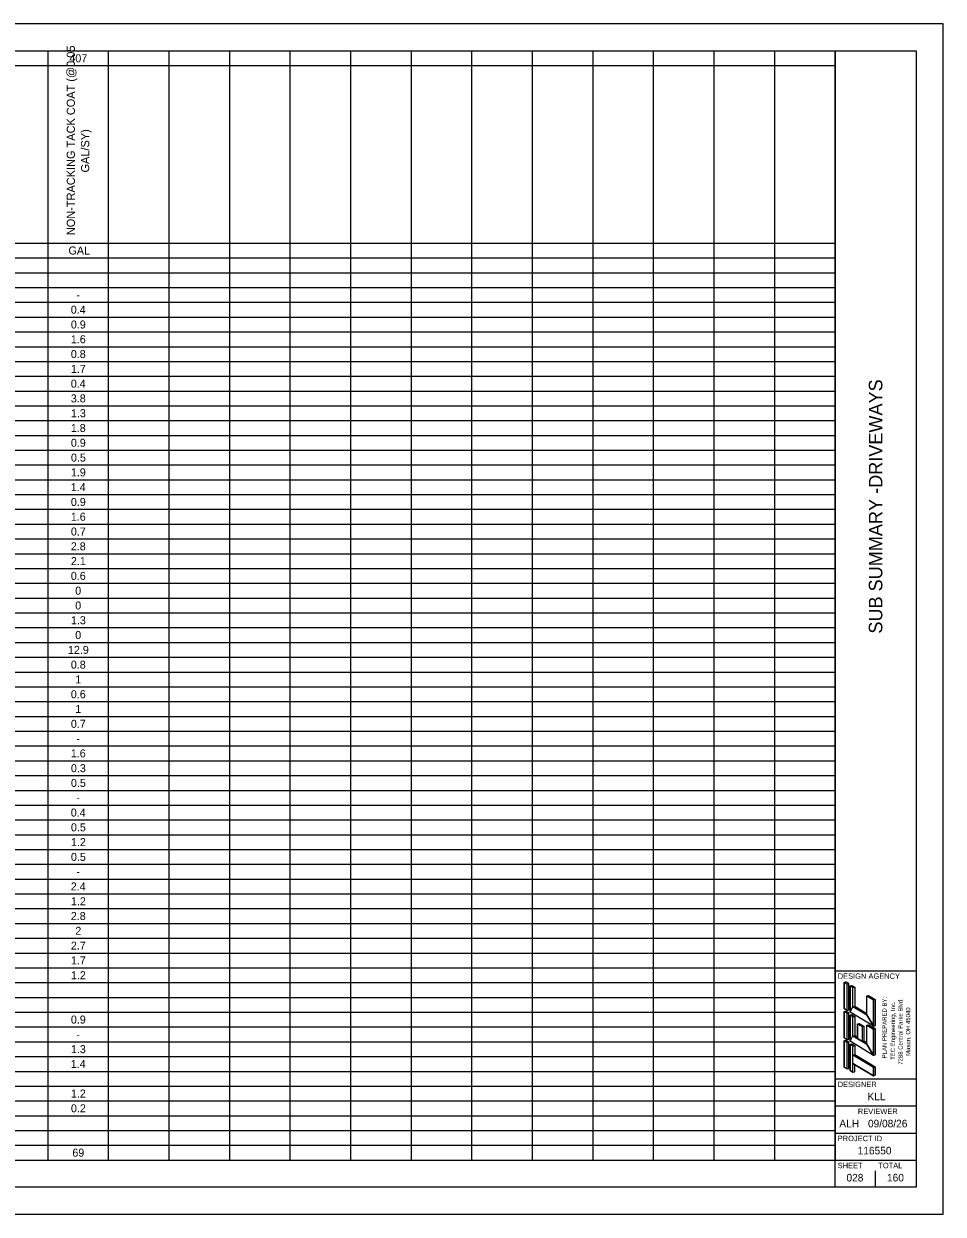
# Model space of a CAD drawing. Extents: x 0 to 34, y 0 to 22.
# Drawn here: x 17 to 34, y 0 to 22 of the extents above; entities that cross this region are included whole.
import ezdxf

# ---------------------------------------------------------------- set-up
doc = ezdxf.new("R2010")
doc.units = 0
for name, color, linetype in [('Default', 7, 'Continuous'), ('SH_Border', 7, 'Continuous'), ('SH_Cut_Line', 7, 'Continuous'), ('SH_Data', 7, 'Continuous'), ('SH_Text', 7, 'Continuous')]:
    doc.layers.add(name, color=color, linetype=linetype)

msp = doc.modelspace()

# ---------------------------------------------------------------- linework, layer by layer
at = {"layer": 'SH_Border'}
for p, q in [((32, 0.5), (32, 21.5)), ((32, 4.5), (33.5, 4.5)), ((32, 2.5), (33.5, 2.5)), ((32, 2), (33.5, 2)), ((32, 1.5), (33.5, 1.5)), ((32, 1), (33.5, 1))]:
    msp.add_line(p, q, dxfattribs=at)
msp.add_lwpolyline([(1.5, 21.5), (33.5, 21.5), (33.5, 0.5), (1.5, 0.5)], close=True, dxfattribs=at)
at = {"layer": 'SH_Cut_Line'}
msp.add_lwpolyline([(0, 0), (34, 0), (34, 22), (0, 22)], close=True, dxfattribs=at)
at = {"layer": 'SH_Data'}
for p, q in [((32.75, 3.5), (32.75, 3.5)), ((32.375, 0.675), (32.375, 0.675)), ((32.75, 0.5), (32.75, 0.8))]:
    msp.add_line(p, q, dxfattribs=at)
at = {"layer": 'SH_Text'}
for p, q in [((1.5, 21.5), (32, 21.5)), ((17.442, 21.5), (17.442, 1)), ((18.562, 21.5), (18.562, 1)), ((19.681, 21.5), (19.681, 1)), ((20.801, 21.5), (20.801, 1)), ((21.921, 21.5), (21.921, 1)), ((23.041, 21.5), (23.041, 1)), ((24.161, 21.5), (24.161, 1)), ((25.281, 21.5), (25.281, 1)), ((26.401, 21.5), (26.401, 1)), ((27.521, 21.5), (27.521, 1)), ((28.64, 21.5), (28.64, 1)), ((29.76, 21.5), (29.76, 1)), ((30.88, 21.5), (30.88, 1)), ((32, 21.5), (32, 1)), ((8.483, 21.227), (32, 21.227)), ((8.483, 17.947), (32, 17.947)), ((1.5, 17.673), (32, 17.673)), ((1.5, 17.4), (32, 17.4)), ((1.5, 17.127), (32, 17.127)), ((1.5, 16.853), (32, 16.853)), ((1.5, 16.58), (32, 16.58)), ((1.5, 16.307), (32, 16.307)), ((1.5, 16.033), (32, 16.033)), ((1.5, 15.76), (32, 15.76)), ((1.5, 15.487), (32, 15.487)), ((1.5, 15.213), (32, 15.213)), ((1.5, 14.94), (32, 14.94)), ((1.5, 14.667), (32, 14.667)), ((1.5, 14.393), (32, 14.393)), ((1.5, 14.12), (32, 14.12)), ((1.5, 13.847), (32, 13.847)), ((1.5, 13.573), (32, 13.573)), ((1.5, 13.3), (32, 13.3)), ((1.5, 13.027), (32, 13.027)), ((1.5, 12.753), (32, 12.753)), ((1.5, 12.48), (32, 12.48)), ((1.5, 12.207), (32, 12.207)), ((1.5, 11.933), (32, 11.933)), ((1.5, 11.66), (32, 11.66)), ((1.5, 11.387), (32, 11.387)), ((1.5, 11.113), (32, 11.113)), ((1.5, 10.84), (32, 10.84)), ((1.5, 10.567), (32, 10.567)), ((1.5, 10.293), (32, 10.293)), ((1.5, 10.02), (32, 10.02)), ((1.5, 9.747), (32, 9.747)), ((1.5, 9.473), (32, 9.473)), ((1.5, 9.2), (32, 9.2)), ((1.5, 8.927), (32, 8.927)), ((1.5, 8.653), (32, 8.653)), ((1.5, 8.38), (32, 8.38)), ((1.5, 8.107), (32, 8.107)), ((1.5, 7.833), (32, 7.833)), ((1.5, 7.56), (32, 7.56)), ((1.5, 7.287), (32, 7.287)), ((1.5, 7.013), (32, 7.013)), ((1.5, 6.74), (32, 6.74)), ((1.5, 6.467), (32, 6.467)), ((1.5, 6.193), (32, 6.193)), ((1.5, 5.92), (32, 5.92)), ((1.5, 5.647), (32, 5.647)), ((1.5, 5.373), (32, 5.373)), ((1.5, 5.1), (32, 5.1)), ((1.5, 4.827), (32, 4.827)), ((1.5, 4.553), (32, 4.553)), ((1.5, 4.28), (32, 4.28)), ((32.169, 4.285), (32.201, 4.294)), ((32.169, 3.799), (32.169, 4.285)), ((32.223, 4.253), (32.169, 4.285)), ((32.255, 4.261), (32.201, 4.294)), ((32.223, 4.253), (32.255, 4.261)), ((32.223, 3.767), (32.223, 4.253)), ((32.255, 3.775), (32.255, 4.261)), ((32.277, 4.221), (32.309, 4.229)), ((32.331, 4.188), (32.277, 4.221)), ((32.277, 3.735), (32.277, 4.221)), ((32.309, 4.229), (32.363, 4.196)), ((32.331, 4.188), (32.363, 4.196)), ((32.331, 3.837), (32.331, 4.188)), ((32.363, 4.196), (32.363, 3.845)), ((1.5, 4.007), (32, 4.007)), ((32.587, 4.034), (32.62, 4.042)), ((32.587, 3.683), (32.587, 4.034)), ((32.709, 3.961), (32.587, 4.034)), ((32.62, 4.042), (32.741, 3.97)), ((32.709, 3.961), (32.741, 3.97)), ((32.709, 3.475), (32.709, 3.961)), ((32.741, 3.97), (32.741, 3.484)), ((32.223, 3.767), (32.169, 3.799)), ((32.169, 3.745), (32.201, 3.754)), ((32.169, 3.259), (32.169, 3.745)), ((32.223, 3.713), (32.169, 3.745)), ((32.255, 3.722), (32.201, 3.754)), ((32.223, 3.767), (32.255, 3.775)), ((32.331, 3.837), (32.363, 3.845)), ((32.587, 3.683), (32.331, 3.837)), ((32.363, 3.845), (32.587, 3.711)), ((1.5, 3.733), (32, 3.733)), ((32.223, 3.713), (32.255, 3.722)), ((32.223, 3.227), (32.223, 3.713)), ((32.255, 3.236), (32.255, 3.722)), ((32.709, 3.475), (32.277, 3.735)), ((32.277, 3.681), (32.309, 3.689)), ((32.277, 3.195), (32.277, 3.681)), ((32.331, 3.648), (32.277, 3.681)), ((32.309, 3.689), (32.363, 3.656)), ((32.331, 3.648), (32.363, 3.656)), ((32.331, 3.297), (32.331, 3.648)), ((32.363, 3.656), (32.363, 3.305)), ((32.415, 3.519), (32.448, 3.527)), ((32.448, 3.527), (32.535, 3.474)), ((1.5, 3.46), (32, 3.46)), ((32.331, 3.297), (32.363, 3.305)), ((32.363, 3.305), (32.415, 3.274)), ((32.415, 3.519), (32.415, 3.247)), ((32.415, 3.519), (32.503, 3.466)), ((32.503, 3.466), (32.535, 3.474)), ((32.503, 3.466), (32.503, 3.194)), ((32.535, 3.474), (32.535, 3.202)), ((32.587, 3.494), (32.62, 3.502)), ((32.587, 3.143), (32.587, 3.494)), ((32.709, 3.421), (32.587, 3.494)), ((32.62, 3.502), (32.741, 3.43)), ((32.709, 3.475), (32.741, 3.484)), ((32.709, 3.421), (32.741, 3.43)), ((32.709, 2.935), (32.709, 3.421)), ((32.741, 3.43), (32.741, 2.944)), ((1.5, 3.187), (32, 3.187)), ((32.223, 3.227), (32.169, 3.259)), ((32.169, 3.205), (32.201, 3.215)), ((32.169, 2.719), (32.169, 3.205)), ((32.223, 3.173), (32.169, 3.205)), ((32.255, 3.181), (32.201, 3.215)), ((32.222, 3.173), (32.255, 3.181)), ((32.223, 3.227), (32.255, 3.236)), ((32.223, 2.687), (32.223, 3.173)), ((32.255, 2.695), (32.255, 3.181)), ((32.709, 2.935), (32.277, 3.195)), ((32.277, 3.141), (32.309, 3.151)), ((32.331, 3.108), (32.277, 3.141)), ((32.277, 2.655), (32.277, 3.141)), ((32.309, 3.151), (32.363, 3.116)), ((32.415, 3.247), (32.331, 3.297)), ((32.331, 3.108), (32.363, 3.116)), ((32.331, 2.944), (32.331, 3.108)), ((32.363, 3.116), (32.363, 2.952)), ((32.503, 3.194), (32.535, 3.202)), ((32.587, 3.143), (32.503, 3.194)), ((32.535, 3.202), (32.587, 3.171)), ((1.5, 2.913), (32, 2.913)), ((32.331, 2.944), (32.363, 2.952)), ((32.331, 2.944), (32.709, 2.717)), ((32.363, 2.952), (32.741, 2.725)), ((32.709, 2.935), (32.741, 2.944)), ((1.5, 2.64), (32, 2.64)), ((32.223, 2.687), (32.169, 2.719)), ((32.223, 2.687), (32.255, 2.695)), ((32.331, 2.622), (32.277, 2.655)), ((32.331, 2.787), (32.709, 2.56)), ((32.331, 2.622), (32.331, 2.787)), ((32.363, 2.63), (32.363, 2.767)), ((32.709, 2.717), (32.741, 2.725)), ((32.709, 2.56), (32.709, 2.717)), ((32.741, 2.725), (32.741, 2.568)), ((32.331, 2.622), (32.363, 2.63)), ((32.709, 2.56), (32.741, 2.568)), ((1.5, 2.367), (32, 2.367)), ((1.5, 2.093), (32, 2.093)), ((1.5, 1.82), (32, 1.82)), ((1.5, 1.547), (32, 1.547)), ((1.5, 1.273), (32, 1.273)), ((1.5, 1), (32, 1))]:
    msp.add_line(p, q, dxfattribs=at)
for points in [[(32.169, 3.799), (32.223, 3.767), (32.223, 4.253), (32.169, 4.285)], [(32.277, 3.735), (32.331, 3.837), (32.331, 4.188), (32.277, 4.221)], [(32.709, 3.475), (32.587, 3.683), (32.587, 4.034), (32.709, 3.961)], [(32.169, 3.259), (32.223, 3.227), (32.223, 3.713), (32.169, 3.745)], [(32.277, 3.735), (32.331, 3.837), (32.587, 3.683), (32.709, 3.475)], [(32.277, 3.195), (32.331, 3.297), (32.331, 3.648), (32.277, 3.681)], [(32.415, 3.247), (32.415, 3.519), (32.503, 3.466), (32.503, 3.194)], [(32.709, 2.935), (32.587, 3.143), (32.587, 3.494), (32.709, 3.421)], [(32.169, 2.719), (32.223, 2.687), (32.223, 3.173), (32.169, 3.205)], [(32.277, 3.195), (32.331, 3.297), (32.587, 3.143), (32.709, 2.935)], [(32.277, 2.655), (32.331, 2.622), (32.331, 3.108), (32.277, 3.141)], [(32.331, 2.787), (32.331, 2.944), (32.709, 2.717), (32.709, 2.56)]]:
    msp.add_lwpolyline(points, close=True, dxfattribs=at)

# ---------------------------------------------------------------- texts
at = {"layer": 'Default'}
for s, p in [('PLAN PREPARED BY:', (32.954, 2.88)), ('TEC Engineering, Inc.', (33.11, 2.851)), ('7288 Central Parke Blvd.', (33.25, 2.762)), ('Mason, OH 45040', (33.39, 2.925))]:
    msp.add_text(s, height=0.08, rotation=90, dxfattribs=at).set_placement(p)
at = {"layer": 'SH_Data'}
msp.add_text('SUB SUMMARY -DRIVEWAYS', height=0.25, rotation=90, dxfattribs=at).set_placement((32.875, 10.73))
for s, height, p in [('DESIGN AGENCY', 0.1, (32.05, 4.35)), ('DESIGNER', 0.1, (32.05, 2.35)), ('KLL', 0.14, (32.601, 2.105)), ('REVIEWER', 0.1, (32.422, 1.85)), ('ALH', 0.14, (32.08, 1.605)), ('09/08/26', 0.14, (32.609, 1.605)), ('PROJECT ID', 0.1, (32.05, 1.35)), ('116550', 0.14, (32.419, 1.105)), ('SHEET', 0.1, (32.05, 0.85)), ('TOTAL', 0.1, (32.8, 0.85)), ('028', 0.14, (32.212, 0.605)), ('160', 0.14, (32.961, 0.605))]:
    msp.add_text(s, height=height, dxfattribs=at).set_placement(p)
at = {"layer": 'SH_Text'}
for s, height, p in [('NON-TRACKING TACK COAT (@0.05 ', 0.15151, (17.945, 18.094)), ('GAL/SY)', 0.1515, (18.21, 19.252))]:
    msp.add_text(s, height=height, rotation=90, dxfattribs=at).set_placement(p)
for s, height, p in [('407', 0.1479, (17.843, 21.289)), ('GAL', 0.1479, (17.827, 17.736)), ('-', 0.148, (17.972, 16.916)), ('0.4', 0.1479, (17.869, 16.643)), ('0.9', 0.1479, (17.871, 16.369)), ('1.6', 0.1479, (17.87, 16.096)), ('0.8', 0.1479, (17.87, 15.823)), ('1.7', 0.1479, (17.871, 15.549)), ('0.4', 0.1479, (17.869, 15.276)), ('3.8', 0.1479, (17.87, 15.003)), ('1.3', 0.1479, (17.872, 14.729)), ('1.8', 0.1479, (17.87, 14.456)), ('0.9', 0.1479, (17.871, 14.183)), ('0.5', 0.1479, (17.872, 13.909)), ('1.9', 0.1479, (17.871, 13.636)), ('1.4', 0.1479, (17.869, 13.363)), ('0.9', 0.1479, (17.871, 13.089)), ('1.6', 0.1479, (17.87, 12.816)), ('0.7', 0.1479, (17.871, 12.543)), ('2.8', 0.1479, (17.87, 12.269)), ('2.1', 0.1479, (17.871, 11.996)), ('0.6', 0.1479, (17.87, 11.723)), ('0', 0.148, (17.951, 11.449)), ('0', 0.148, (17.951, 11.176)), ('1.3', 0.1479, (17.872, 10.903)), ('0', 0.148, (17.951, 10.629)), ('12.9', 0.1479, (17.817, 10.356)), ('0.8', 0.1479, (17.87, 10.083)), ('1', 0.148, (17.953, 9.809)), ('0.6', 0.1479, (17.87, 9.536)), ('1', 0.148, (17.953, 9.263)), ('0.7', 0.1479, (17.871, 8.989)), ('1.6', 0.1479, (17.87, 8.443)), ('-', 0.148, (17.972, 8.716)), ('0.3', 0.1479, (17.872, 8.169)), ('0.5', 0.1479, (17.872, 7.896)), ('0.4', 0.1479, (17.869, 7.349)), ('-', 0.148, (17.972, 7.623)), ('0.5', 0.1479, (17.872, 7.076)), ('1.2', 0.1479, (17.872, 6.803)), ('0.5', 0.1479, (17.872, 6.529)), ('-', 0.148, (17.972, 6.256)), ('2.4', 0.1479, (17.869, 5.983)), ('1.2', 0.1479, (17.872, 5.709)), ('2.8', 0.1479, (17.87, 5.436)), ('2', 0.148, (17.953, 5.163)), ('2.7', 0.1479, (17.871, 4.889)), ('1.7', 0.1479, (17.871, 4.616)), ('1.2', 0.1479, (17.872, 4.343)), ('0.9', 0.1479, (17.871, 3.523)), ('-', 0.148, (17.972, 3.249)), ('1.3', 0.1479, (17.872, 2.976)), ('1.4', 0.1479, (17.869, 2.703)), ('1.2', 0.1479, (17.872, 2.156)), ('0.2', 0.1479, (17.872, 1.883)), ('69', 0.1479, (17.898, 1.063))]:
    msp.add_text(s, height=height, dxfattribs=at).set_placement(p)

doc.saveas('drawing.dxf')
